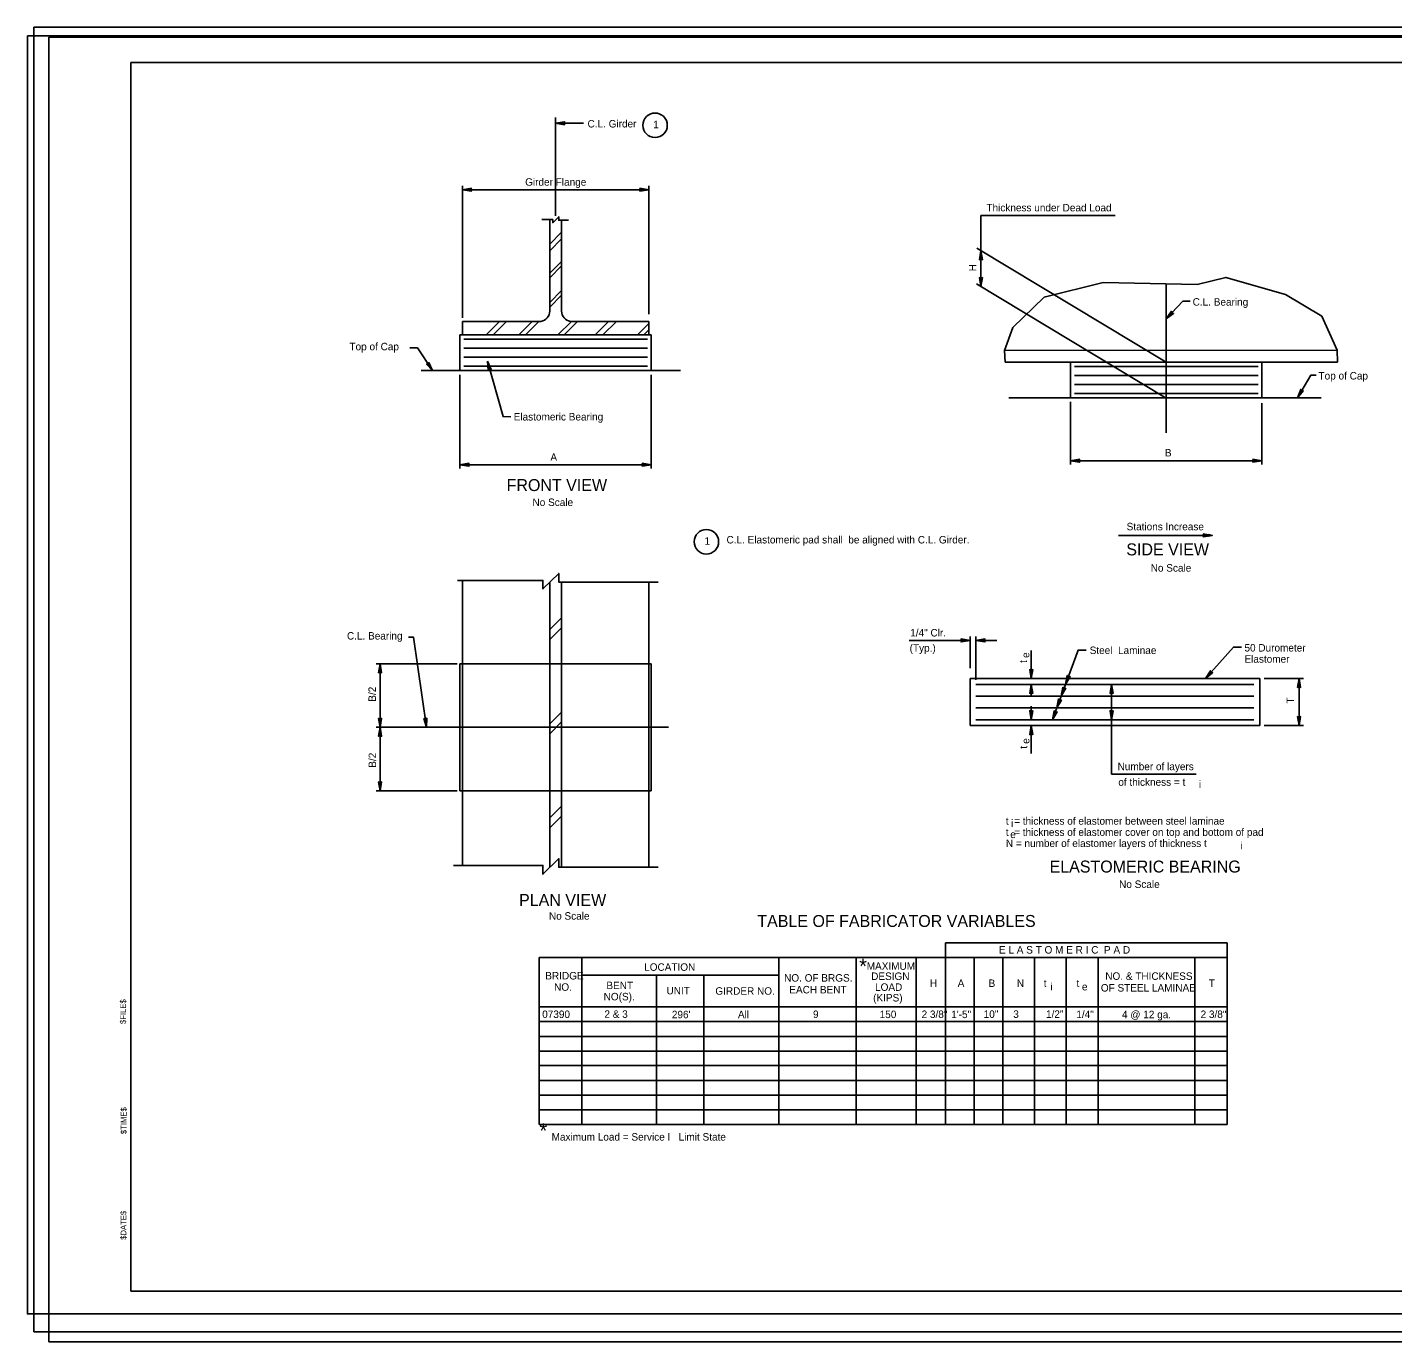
# Model space of a CAD drawing. Extents: x -194 to 226, y 505 to 725.
# Drawn here: x -193.6 to 34.6, y 505.4 to 725.2 of the extents above; entities that cross this region are included whole.
import ezdxf

# ---------------------------------------------------------------- set-up
doc = ezdxf.new("R2010")
doc.units = 0
for name, color, linetype in [('border', 7, 'Continuous'), ('Border 2660-Hwy18 - Level 62', 7, 'Continuous'), ('Border 2660-Hwy18 - Level 63', 7, 'Continuous'), ('Dimensions', 7, 'Continuous'), ('Level 20', 7, 'Continuous'), ('Level 21', 7, 'Continuous'), ('Level 31', 7, 'Continuous'), ('Level 40', 7, 'Continuous'), ('Level 41', 7, 'Continuous'), ('Level 42', 7, 'Continuous'), ('Level 43', 7, 'Continuous'), ('Level 58', 7, 'Continuous'), ('Level 62 PDF', 7, 'Continuous')]:
    doc.layers.add(name, color=color, linetype=linetype)

# ---------------------------------------------------------------- blocks, each defined once
blk = doc.blocks.new('ARROW')
at = {"layer": 'Level 58'}
blk.add_lwpolyline([(-1.2, 0.251), (0, 0), (-1.2, -0.251), (-1.004, 0)], close=True, dxfattribs=at)

msp = doc.modelspace()

# ---------------------------------------------------------------- linework, layer by layer
at = {"layer": 'border'}
for p, q in [((-176.33, 719.31), (143.78, 719.31)), ((-176.33, 513.86), (-176.33, 719.31)), ((143.78, 513.86), (-176.33, 513.86))]:
    msp.add_line(p, q, dxfattribs=at)
at = {"layer": 'Border 2660-Hwy18 - Level 62'}
msp.add_lwpolyline([(-192.53, 725.17), (148.65, 725.17), (148.65, 507.07), (-192.53, 507.07)], close=True, dxfattribs=at)
at = {"layer": 'Border 2660-Hwy18 - Level 63'}
msp.add_lwpolyline([(-193.64, 723.74), (146.35, 723.74), (146.35, 510.04), (-193.64, 510.04)], close=True, dxfattribs=at)
at = {"layer": 'Dimensions'}
for p, q in [((-129.69, 671.58), (-128.41, 671.58)), ((-128.41, 671.58), (-125.92, 667.79))]:
    msp.add_line(p, q, dxfattribs=at)
msp.add_lwpolyline([(-125.92, 667.79), (-126.51, 669.12), (-126.64, 668.89), (-126.91, 668.86)], close=True, dxfattribs=at)
at = {"layer": 'Level 20'}
for p, q in [((-105.35, 693.67), (-105.35, 710.08)), ((-3.29, 657.38), (-3.29, 682.35)), ((-135.32, 608.13), (-86.47, 608.13))]:
    msp.add_line(p, q, dxfattribs=at)
at = {"layer": 'Level 21'}
for p, q in [((-84.47, 667.79), (-127.81, 667.79)), ((22.62, 663.21), (-29.62, 663.21))]:
    msp.add_line(p, q, dxfattribs=at)
at = {"layer": 'Level 31'}
for p, q in [((-106.33, 693.03), (-106.33, 677.74)), ((-104.36, 692.92), (-104.36, 677.74)), ((-107.8, 675.98), (-120.93, 675.98)), ((-120.93, 673.75), (-120.93, 675.98)), ((-102.89, 675.98), (-89.76, 675.98)), ((-89.76, 673.75), (-89.76, 675.98)), ((-121.33, 673.75), (-104.36, 673.75)), ((-121.33, 667.79), (-121.33, 673.75)), ((-89.37, 673.75), (-106.33, 673.75)), ((-89.37, 667.79), (-89.37, 673.75)), ((-120.68, 673.01), (-90.01, 673.01)), ((-120.68, 671.52), (-90.01, 671.52)), ((-30.3, 671.15), (25.29, 671.16)), ((-120.68, 670.02), (-90.01, 670.02)), ((-30.24, 669.17), (25.35, 669.19)), ((-19.27, 663.21), (-19.27, 669.17)), ((12.69, 663.21), (12.69, 669.17)), ((-120.68, 668.53), (-90.01, 668.53)), ((-18.62, 668.43), (12.05, 668.43)), ((-18.62, 666.94), (12.05, 666.94)), ((-18.62, 665.45), (12.05, 665.45)), ((-18.62, 663.95), (12.05, 663.95)), ((-120.93, 585.03), (-120.93, 632.7)), ((-106.33, 632.38), (-106.33, 584.69)), ((-104.36, 632.42), (-104.36, 584.74)), ((-89.76, 584.74), (-89.76, 632.42)), ((-121.33, 618.76), (-121.33, 597.5)), ((-120.93, 618.76), (-121.33, 618.76)), ((-120.93, 618.76), (-89.76, 618.76)), ((-89.76, 618.76), (-89.37, 618.76)), ((-89.37, 618.76), (-89.37, 597.5)), ((-36.07, 616.29), (12.33, 616.29)), ((-36.07, 616.29), (-36.07, 608.42)), ((12.33, 616.29), (12.33, 608.42)), ((-35.09, 615.31), (11.33, 615.31)), ((-35.09, 613.34), (-20.87, 613.34)), ((-20.87, 613.34), (11.33, 613.34)), ((-35.09, 611.37), (11.33, 611.37)), ((-35.09, 609.4), (-22.31, 609.4)), ((-22.31, 609.4), (11.33, 609.4)), ((-36.07, 608.42), (12.33, 608.42)), ((-120.93, 597.5), (-121.33, 597.5)), ((-120.93, 597.5), (-89.76, 597.5)), ((-89.76, 597.5), (-89.37, 597.5))]:
    msp.add_line(p, q, dxfattribs=at)
for centre, start, end in [((-108.1, 677.73), 279.5, 0), ((-102.59, 677.73), 180, 260.5)]:
    msp.add_arc(centre, 1.76, start, end, dxfattribs=at)
at = {"layer": 'Level 40'}
for p, q in [((-100.96, 569.66), (-100.96, 541.74)), ((-68.06, 569.66), (-68.06, 541.74)), ((-55.1, 569.66), (-55.1, 541.74)), ((-45.11, 569.66), (-45.11, 541.74)), ((-35.38, 569.66), (-35.38, 541.74)), ((-30.59, 569.66), (-30.59, 541.74)), ((-25.3, 569.66), (-25.3, 541.74)), ((-20.03, 569.66), (-20.03, 541.74)), ((-14.65, 569.66), (-14.65, 541.74)), ((1.49, 569.66), (1.49, 541.74)), ((-100.96, 566.68), (-68.06, 566.68)), ((-88.46, 566.68), (-88.46, 541.74)), ((-80.56, 566.68), (-80.56, 541.74)), ((-108.12, 561.37), (6.87, 561.37)), ((6.87, 561.87), (6.87, 558.38)), ((-108.12, 558.92), (6.87, 558.92)), ((-108.12, 556.46), (6.87, 556.46)), ((-108.12, 554.01), (6.87, 554.01)), ((-108.12, 551.56), (6.87, 551.56)), ((-108.12, 549.1), (6.87, 549.1)), ((-108.12, 546.65), (6.87, 546.65)), ((-108.12, 544.2), (6.87, 544.2))]:
    msp.add_line(p, q, dxfattribs=at)
for centre in [(-88.73, 708.78), (-80.15, 639.15)]:
    msp.add_circle(centre, 2.05, dxfattribs=at)
at = {"layer": 'Level 41'}
for p, q in [((-40.17, 572.11), (-40.17, 541.74)), ((-40.17, 572.11), (6.87, 572.11)), ((6.87, 572.11), (6.87, 541.74)), ((-108.12, 569.66), (6.87, 569.66)), ((-108.12, 569.66), (-108.12, 541.74)), ((-108.12, 541.74), (6.87, 541.74))]:
    msp.add_line(p, q, dxfattribs=at)
at = {"layer": 'Level 42'}
for p, q in [((-106.33, 688.92), (-104.36, 690.89)), ((-106.33, 687.82), (-104.36, 689.81)), ((-106.33, 684.07), (-104.36, 686.03)), ((-106.33, 683.3), (-104.36, 685.27)), ((-106.33, 679.18), (-104.36, 681.15)), ((-106.33, 678.37), (-104.36, 680.37)), ((-116.93, 673.75), (-114.7, 675.98)), ((-115.8, 673.75), (-113.57, 675.98)), ((-111.5, 673.75), (-109.28, 675.98)), ((-110.4, 673.75), (-108.18, 675.98)), ((-104.95, 673.75), (-102.71, 675.98)), ((-103.92, 673.75), (-101.69, 675.98)), ((-98.73, 673.75), (-96.52, 675.98)), ((-97.43, 673.75), (-95.2, 675.98)), ((-91.64, 673.75), (-89.76, 675.66)), ((-90.59, 673.75), (-89.76, 674.59)), ((-106.33, 624.46), (-104.36, 626.43)), ((-106.33, 622.79), (-104.36, 624.78)), ((-106.33, 608.72), (-104.36, 610.69)), ((-106.33, 607.04), (-104.36, 609.04)), ((-106.33, 592.98), (-104.36, 594.94)), ((-106.33, 591.3), (-104.36, 593.29))]:
    msp.add_line(p, q, dxfattribs=at)
at = {"layer": 'Level 43'}
for p, q in [((-100.7, 709.12), (-105.35, 709.12)), ((-120.93, 676.61), (-120.93, 698.64)), ((-89.76, 677.19), (-89.76, 698.64)), ((-120.93, 698), (-89.76, 698)), ((-11.84, 693.7), (-34.28, 693.7)), ((-34.28, 693.7), (-34.28, 691.97)), ((-34.28, 681.83), (-34.28, 691.97)), ((-3.29, 669.17), (-34.96, 688.23)), ((-3.29, 663.18), (-35, 682.26)), ((-121.33, 667.04), (-121.33, 651.4)), ((-89.37, 667.04), (-89.37, 651.4)), ((-19.27, 662.56), (-19.27, 652.06)), ((12.69, 662.31), (12.69, 652.06)), ((-19.27, 652.71), (12.69, 652.71)), ((-121.33, 652.04), (-89.37, 652.04)), ((-36.07, 618.02), (-36.07, 623.31)), ((-35.09, 616.05), (-35.09, 623.31)), ((-46.28, 622.67), (-36.07, 622.67)), ((-31.6, 622.67), (-35.09, 622.67)), ((-25.85, 621), (-25.85, 616.29)), ((-121.82, 618.76), (-135.32, 618.76)), ((-134.68, 608.13), (-134.68, 618.76)), ((13.06, 616.29), (19.66, 616.29)), ((18.91, 608.42), (18.91, 616.29)), ((-25.85, 615.31), (-25.85, 613.23)), ((-12.42, 607.44), (-12.42, 615.31)), ((-25.85, 609.4), (-25.85, 611.68)), ((-134.68, 597.5), (-134.68, 608.13)), ((-25.85, 603.73), (-25.85, 608.42)), ((-12.42, 607.44), (-12.42, 600.28)), ((13.06, 608.42), (19.66, 608.42)), ((-12.42, 600.28), (1.69, 600.28)), ((-121.79, 597.5), (-135.32, 597.5))]:
    msp.add_line(p, q, dxfattribs=at)
for points in [[(-105.35, 709.12), (-103.85, 708.87), (-103.98, 709.12), (-103.85, 709.37)], [(-120.93, 698), (-119.43, 697.75), (-119.56, 698), (-119.43, 698.25)], [(-89.76, 698), (-91.26, 698.25), (-91.13, 698), (-91.26, 697.75)], [(-34.28, 687.81), (-34.53, 686.31), (-34.28, 686.44), (-34.03, 686.31)], [(-34.28, 681.83), (-34.03, 683.33), (-34.28, 683.2), (-34.53, 683.33)], [(-3.29, 676.42), (-2.08, 677.34), (-2.35, 677.42), (-2.44, 677.68)], [(-116.74, 669.37), (-116.62, 667.86), (-116.41, 668.04), (-116.13, 667.98)], [(18.64, 663.21), (19.61, 664.37), (19.33, 664.39), (19.18, 664.63)], [(-19.27, 652.71), (-17.77, 652.46), (-17.9, 652.71), (-17.77, 652.96)], [(12.69, 652.71), (11.19, 652.96), (11.32, 652.71), (11.19, 652.46)], [(-121.33, 652.04), (-119.83, 651.79), (-119.96, 652.04), (-119.83, 652.29)], [(-89.37, 652.04), (-90.87, 652.29), (-90.74, 652.04), (-90.87, 651.79)], [(4.39, 640.22), (2.89, 640.47), (3.02, 640.22), (2.89, 639.97)], [(-36.07, 622.67), (-37.57, 622.92), (-37.44, 622.67), (-37.57, 622.42)], [(-35.09, 622.67), (-33.59, 622.42), (-33.72, 622.67), (-33.59, 622.92)], [(-134.68, 618.76), (-134.93, 617.26), (-134.68, 617.39), (-134.43, 617.26)], [(-25.85, 616.29), (-25.6, 617.79), (-25.85, 617.66), (-26.1, 617.79)], [(-20.12, 615.31), (-19.37, 616.63), (-19.65, 616.59), (-19.84, 616.8)], [(3.27, 616.29), (4.46, 617.25), (4.18, 617.32), (4.08, 617.58)], [(18.91, 616.29), (18.66, 614.79), (18.91, 614.92), (19.16, 614.79)], [(-25.85, 615.31), (-26.1, 613.81), (-25.85, 613.94), (-25.6, 613.81)], [(-20.84, 613.34), (-20.09, 614.66), (-20.37, 614.63), (-20.56, 614.83)], [(-12.42, 615.31), (-12.67, 613.81), (-12.42, 613.94), (-12.17, 613.81)], [(-21.56, 611.37), (-20.81, 612.69), (-21.09, 612.66), (-21.28, 612.87)], [(-134.68, 608.13), (-134.43, 609.63), (-134.68, 609.5), (-134.93, 609.63)], [(-126.9, 608.13), (-126.87, 609.65), (-127.09, 609.49), (-127.36, 609.58)], [(-25.85, 609.4), (-25.6, 610.9), (-25.85, 610.77), (-26.1, 610.9)], [(-22.28, 609.4), (-21.53, 610.73), (-21.81, 610.69), (-22, 610.9)], [(-12.42, 609.4), (-12.17, 610.9), (-12.42, 610.77), (-12.67, 610.9)], [(18.91, 608.42), (19.16, 609.92), (18.91, 609.79), (18.66, 609.92)], [(-134.68, 608.13), (-134.93, 606.63), (-134.68, 606.76), (-134.43, 606.63)], [(-25.85, 608.42), (-26.1, 606.92), (-25.85, 607.05), (-25.6, 606.92)], [(-134.68, 597.5), (-134.43, 599), (-134.68, 598.87), (-134.93, 599)]]:
    msp.add_lwpolyline(points, close=True, dxfattribs=at)
for points in [[(-107.66, 693.03), (-105.84, 693.03), (-105.84, 692.48), (-104.83, 693.49), (-104.83, 692.92), (-103.19, 692.92)], [(-30.24, 669.17), (-30.3, 671.13), (-28.92, 674.99), (-23.67, 680.04), (-13.85, 682.48), (1.87, 682.19), (6.66, 683.36), (16.66, 680.5), (22.71, 676.85), (25.29, 671.16), (25.35, 669.19)], [(0.68, 679.37), (-0.51, 679.37), (-3.29, 676.42)], [(-116.74, 669.37), (-114.12, 660.07), (-112.81, 660.06)], [(21.79, 667.02), (20.88, 667.02), (18.64, 663.21)], [(-11.26, 640.22), (4.39, 640.22)], [(-121.72, 632.7), (-107.46, 632.7), (-107.46, 631.26), (-104.83, 633.87), (-104.83, 632.42), (-88.23, 632.42)], [(-129.95, 623.21), (-129.11, 623.21), (-126.9, 608.13)], [(-20.12, 615.31), (-18.03, 621.01), (-16.69, 621.01)], [(3.27, 616.29), (7.92, 621.54), (9.26, 621.54)], [(-20.84, 613.34), (-20.12, 615.31)], [(-21.56, 611.37), (-20.84, 613.34)], [(-22.28, 609.4), (-21.56, 611.37)], [(-122.39, 585.03), (-107.46, 585.03), (-107.46, 583.57), (-104.83, 586.18), (-104.83, 584.74), (-88.23, 584.74)]]:
    msp.add_lwpolyline(points, dxfattribs=at)
at = {"layer": 'Level 62 PDF'}
msp.add_lwpolyline([(-190.03, 723.5), (151.15, 723.5), (151.15, 505.41), (-190.03, 505.41)], close=True, dxfattribs=at)

# ---------------------------------------------------------------- block references
at = {"layer": 'Level 43', "xscale": 0.5247989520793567, "yscale": 0.5247989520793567}
msp.add_blockref('ARROW', (4.39, 640.22), dxfattribs=at)

# ---------------------------------------------------------------- texts
at = {"layer": 'border'}
for s, p in [('$FILE$', (-177.16, 558.52)), ('$TIME$', (-177.06, 540.11)), ('$DATE$', (-177.1, 522.44))]:
    msp.add_text(s, height=0.96, rotation=89.9999, dxfattribs=at).set_placement(p)
at = {"layer": 'Level 40'}
for s, height, p in [('C.L. Girder', 1.25, (-100.01, 708.42)), ('1', 1.25, (-89.04, 708.3)), ('Girder Flange', 1.25, (-110.44, 698.68)), ('Thickness under Dead Load', 1.25, (-33.34, 694.39)), ('C.L. Bearing', 1.25, (1.12, 678.63)), ('Top of Cap', 1.25, (-139.8, 671.17)), ('Top of Cap', 1.25, (22.16, 666.28)), ('Elastomeric Bearing', 1.25, (-112.35, 659.43)), ('A', 1.25, (-106.22, 652.69)), ('B', 1.25, (-3.51, 653.41)), ('No Scale', 1.25, (-109.21, 645.13)), ('Stations Increase', 1.25, (-9.91, 641.07)), ('1', 1.25, (-80.46, 638.66)), ('C.L. Elastomeric pad shall  be aligned with C.L. Girder.', 1.25, (-76.78, 638.87)), ('No Scale', 1.25, (-5.89, 634.16)), ('C.L. Bearing', 1.25, (-140.22, 622.8)), ('1/4" Clr.', 1.25, (-46.08, 623.32)), ('(Typ.)', 1.25, (-46.18, 620.77)), ('Steel  Laminae', 1.25, (-16.09, 620.38)), ('50 Durometer', 1.25, (9.78, 620.8)), ('Elastomer', 1.25, (9.78, 618.93)), ('Number of layers', 1.25, (-11.42, 600.96)), ('of thickness = t', 1.25, (-11.3, 598.35)), ('i', 1.25, (2.17, 597.99)), ('t  = thickness of elastomer between steel laminae', 1.25, (-30.1, 591.85)), ('t  = thickness of elastomer cover on top and bottom of pad', 1.25, (-30.1, 589.98)), ('i', 1.25, (-29.24, 591.47)), ('N = number of elastomer layers of thickness t', 1.25, (-30.1, 588.12)), ('e', 1.25, (-29.36, 589.6)), ('i', 1.25, (9.07, 587.72)), ('No Scale', 1.25, (-11.17, 581.27)), ('No Scale', 1.25, (-106.46, 575.97)), ('E L A S T O M E R I C  P A D', 1.25, (-31.25, 570.3)), ('LOCATION', 1.25, (-90.55, 567.42)), ('*', 2.5, (-54.62, 566.95)), ('MAXIMUM', 1.25, (-53.35, 567.59)), ('BRIDGE', 1.25, (-107.07, 565.97)), ('NO. OF BRGS.', 1.25, (-67.16, 565.61)), ('DESIGN', 1.25, (-52.61, 565.89)), ('H', 1.25, (-42.79, 564.72)), ('A', 1.25, (-38.15, 564.72)), ('B', 1.25, (-32.99, 564.72)), ('N', 1.25, (-28.26, 564.72)), ('NO. & THICKNESS', 1.25, (-13.48, 565.91)), ('T', 1.25, (3.83, 564.72)), ('NO.', 1.25, (-105.6, 564.08)), ('NO(S).', 1.25, (-97.32, 562.48)), ('BENT', 1.25, (-96.86, 564.35)), ('UNIT', 1.25, (-86.82, 563.48)), ('GIRDER NO.', 1.25, (-78.65, 563.42)), ('EACH BENT', 1.25, (-66.29, 563.64)), ('LOAD', 1.25, (-51.96, 564.07)), ('t ', 1.25, (-23.76, 564.72)), ('i', 1.25, (-22.65, 564.14)), ('t ', 1.25, (-18.29, 564.72)), ('e', 1.25, (-17.38, 564.14)), ('OF STEEL LAMINAE', 1.25, (-14.22, 563.95)), ('(KIPS)', 1.25, (-52.28, 562.29)), ('07390', 1.25, (-107.59, 559.53)), ('2 & 3', 1.25, (-97.19, 559.56)), ("296'", 1.25, (-85.92, 559.49)), ('All', 1.25, (-74.88, 559.49)), ('9', 1.25, (-62.33, 559.53)), ('150', 1.25, (-51.19, 559.51)), ('2 3/8"', 1.25, (-44.18, 559.53)), ('1\'-5"', 1.25, (-39.23, 559.51)), ('10"', 1.25, (-33.81, 559.55)), ('3', 1.25, (-28.86, 559.55)), ('1/2"', 1.25, (-23.39, 559.55)), ('1/4"', 1.25, (-18.32, 559.52)), ('4 @ 12 ga.', 1.25, (-10.69, 559.49)), ('2 3/8"', 1.25, (2.45, 559.53)), ('*', 2.5, (-108.05, 539.44)), ('Maximum Load = Service I   Limit State', 1.25, (-106.01, 539.03))]:
    msp.add_text(s, height=height, dxfattribs=at).set_placement(p)
for s, p in [('H', (-35.02, 684.37)), ('t', (-26.55, 618.9)), ('e', (-26.18, 619.73)), ('B/2', (-135.38, 612.41)), ('T', (18.06, 612.09)), ('t', (-26.53, 604.55)), ('e', (-26.16, 605.37)), ('B/2', (-135.35, 601.37))]:
    msp.add_text(s, height=1.25, rotation=90, dxfattribs=at).set_placement(p)
at = {"layer": 'Level 41'}
for s, p in [(' FRONT VIEW ', (-114.28, 647.63)), (' SIDE VIEW ', (-10.71, 636.88)), (' ELASTOMERIC BEARING ', (-23.54, 583.85)), (' PLAN VIEW ', (-112.2, 578.26)), (' TABLE OF FABRICATOR VARIABLES ', (-72.38, 574.75))]:
    msp.add_text(s, height=2, dxfattribs=at).set_placement(p)

doc.saveas('drawing.dxf')
